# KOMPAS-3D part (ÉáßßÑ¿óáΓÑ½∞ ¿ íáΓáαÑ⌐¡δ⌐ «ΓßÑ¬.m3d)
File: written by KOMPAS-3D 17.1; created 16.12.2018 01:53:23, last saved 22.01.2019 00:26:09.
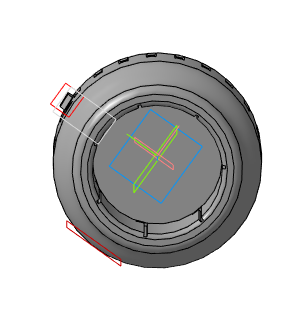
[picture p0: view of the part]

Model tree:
1. тело
2. Операция вращения:1
     Толщина стенки 1 = 0.0001; Угол 1 = 360
3. Плоскость Профиль направляющей проводки
     Расстояние = 3
4. Скругление:30
     Радиус = 0.4
5. Вентеляционное отверстие
6. Вырезать элемент выдавливания:3
     Расстояние 1 = 5
7. Массив по концентрической сетке:9  (with: Вырезать элемент выдавливания:3, Смещенная плоскость:2, Операция вращения:1)  (25 pattern instances)
     Шаг 2 = 360
8. Вентеляционное отверстие(повторно)
9. Вырезать элемент выдавливания:4
     Расстояние 1 = 4
10. Ступица соединительного замка
11. Вырезать элемент выдавливания:5
     Расстояние 1 = 3
12. Паз 1
13. Вырезать элемент выдавливания:6
     Расстояние 2 = 3
14. Паз 2
15. Вырезать элемент вращения:1
     Угол 2 = 5
16. Паз 3
17. Вырезать элемент вращения:2
     Угол 2 = 5
18. Паз 4
19. Вырезать элемент вращения:3
     Угол 2 = 5
20. Паз 5
21. Вырезать элемент вращения:4
     Угол 2 = 5
22. Паз 6
23. Вырезать элемент вращения:5
     Угол 2 = 5
24. Эскиз:1
25. Вырезать элемент выдавливания:7
     Расстояние 1 = 51
26. Эскиз:2
27. Вырезать элемент вращения:6
     Угол 1 = 10
28. Эскиз:4
29. Вырезать элемент вращения:8
     Угол 1 = 10
30. Эскиз:5
31. Вырезать элемент вращения:9
     Угол 1 = 10
32. Эскиз:6
33. Вырезать элемент вращения:11
     Угол 1 = 10
34. Эскиз:7
35. Вырезать элемент вращения:12
     Угол 1 = 10
36. Эскиз:8
37. Вырезать элемент вращения:13
     Угол 1 = 10
38. Плоскость отверстия под разъём
     Расстояние = 26
39. Отверстие под разъём
40. Вырезать элемент вращения:14
     Угол 1 = 360
41. Эскиз:11
42. Вырезать элемент вращения:15
     Угол 2 = 7.3
43. Скругление:32
     Радиус = 1
44. Подвод проводов
45. Вырезать элемент выдавливания:8
     Расстояние 2 = 15
46. Плоскость текста\внешнего вент канала
     Расстояние = 63
47. Внешний вент канал
48. Вырезать элемент выдавливания:10
     Расстояние 1 = 3
49. Массив по концентрической сетке:10  (with: Вырезать элемент выдавливания:10, Смещенная плоскость:4)  (23 pattern instances)
     Шаг 2 = 360
50. Фаска:5
     Угол = 45; Длина 1 = 1; Длина 2 = 1
51. Фаска:6
     Угол = 45; Длина 1 = 1; Длина 2 = 1
52. Фаска:7
     Угол = 45; Длина 1 = 1; Длина 2 = 1
53. Фаска:8
     Угол = 45; Длина 1 = 1; Длина 2 = 1
54. Фаска:9
     Угол = 45; Длина 1 = 1; Длина 2 = 1
55. Фаска:10
     Угол = 45; Длина 1 = 1; Длина 2 = 1
56. Фаска:11
     Угол = 45; Длина 1 = 1; Длина 2 = 1
57. Фаска:12
     Угол = 45; Длина 1 = 1; Длина 2 = 1
58. Фаска:13
     Угол = 45; Длина 1 = 1; Длина 2 = 1
59. Фаска:14
     Угол = 45; Длина 1 = 1; Длина 2 = 1
60. Фаска:15
     Угол = 45; Длина 1 = 1; Длина 2 = 1
61. Фаска:16
     Угол = 45; Длина 1 = 1; Длина 2 = 1
62. Фаска:17
     Угол = 45; Длина 1 = 1; Длина 2 = 1
63. Фаска:18
     Угол = 45; Длина 1 = 1; Длина 2 = 1
64. Фаска:19
     Угол = 45; Длина 1 = 1; Длина 2 = 1
65. Фаска:20
     Угол = 45; Длина 1 = 1; Длина 2 = 1
66. Фаска:21
     Угол = 45; Длина 1 = 1; Длина 2 = 1
67. Фаска:22
     Угол = 45; Длина 1 = 1; Длина 2 = 1
68. Фаска:23
     Угол = 45; Длина 1 = 1; Длина 2 = 1
69. Фаска:24
     Угол = 45; Длина 1 = 1; Длина 2 = 1
70. Текст
71. Вырезать элемент выдавливания:12
     Расстояние 1 = 2.36846; На расстояние 1 = 1
72. Скругление:39
     Радиус = 2
73. Профиль направляющей проводки
74. Элемент выдавливания:1
     Расстояние 1 = 1; Расстояние 2 = 10
75. Фаска:31
     Угол = 45; Длина 1 = 3; Длина 2 = 3
76. Отверстие под проводку
77. Элемент выдавливания:2
     Расстояние 2 = 10
78. Центровка импеллера
79. Элемент выдавливания:3
     Расстояние 2 = 4
80. Фаска:36
     Угол = 45; Длина 1 = 1; Длина 2 = 1
81. Эскиз:20

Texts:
  Engineered in Russia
